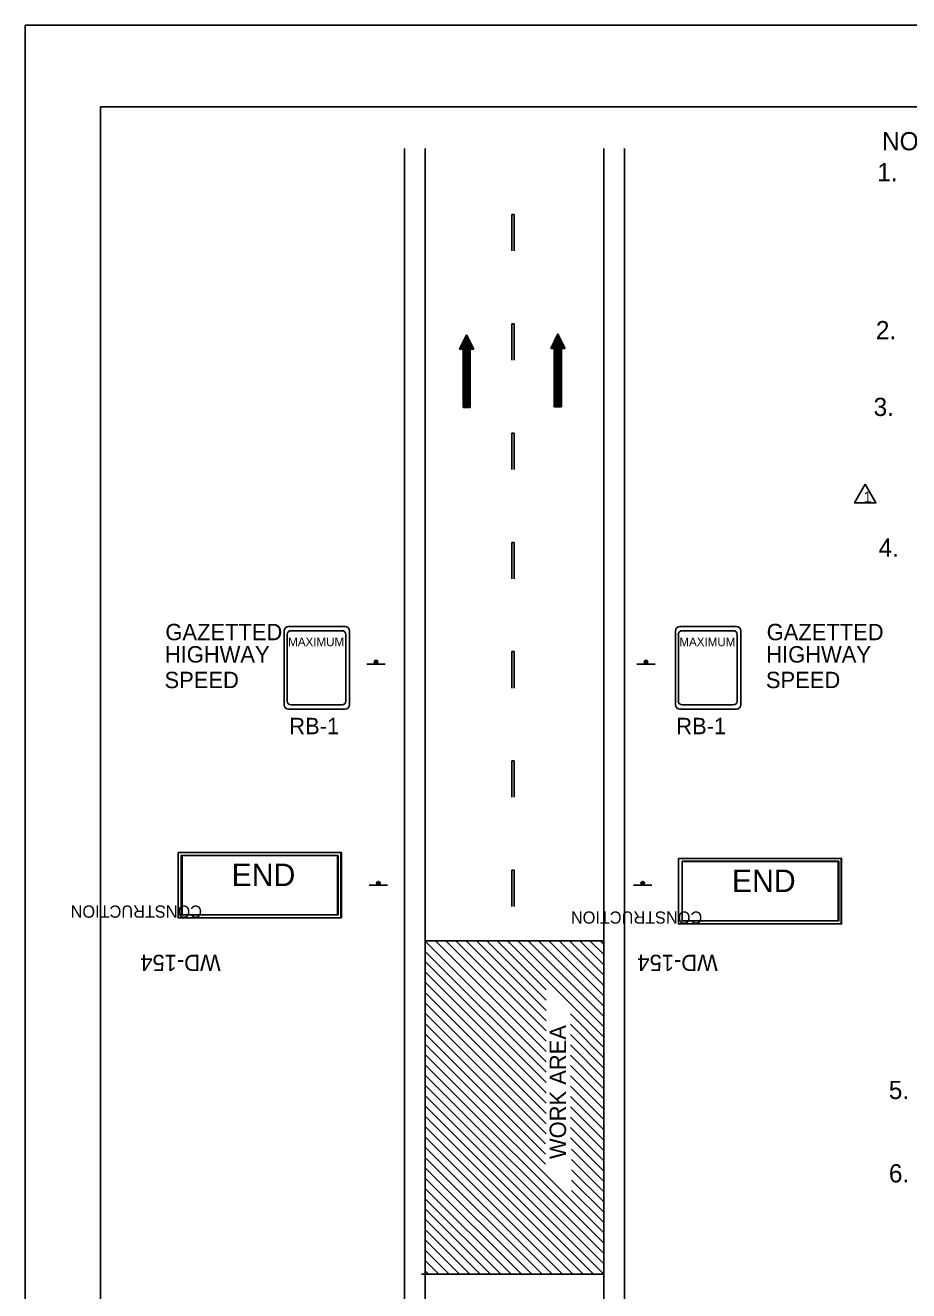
# Model space of a CAD drawing. Extents: x 1381 to 1597, y 125 to 404.
# Drawn here: x 1381.2 to 1498.5, y 235.9 to 403.9 of the extents above; entities that cross this region are included whole.
import ezdxf

# ---------------------------------------------------------------- set-up
doc = ezdxf.new("R2010")
doc.units = 0
for name, color, linetype in [('Level 1', 7, 'Continuous'), ('Level 10', 7, 'Continuous'), ('Level 2', 7, 'Continuous'), ('Level 44', 7, 'Continuous'), ('Level 60', 7, 'Continuous')]:
    doc.layers.add(name, color=color, linetype=linetype)

msp = doc.modelspace()

# ---------------------------------------------------------------- linework, layer by layer
at = {"layer": 'Level 1'}
msp.add_lwpolyline([(1492.72, 342.98), (1491.3, 340.5), (1494.14, 340.5)], close=True, dxfattribs=at)
at = {"layer": 'Level 10'}
for p, q in [((1431.55, 387.59), (1431.55, 334.55)), ((1434.3, 141.65), (1434.3, 387.59)), ((1458.01, 141.65), (1458.01, 387.59)), ((1460.73, 387.59), (1460.73, 387.59)), ((1460.73, 387.59), (1460.73, 141.65)), ((1439.79, 362.84), (1438.82, 360.91)), ((1439.06, 361.39), (1439.06, 360.91)), ((1439.18, 361.63), (1439.18, 360.91)), ((1439.31, 361.87), (1439.31, 353.16)), ((1439.43, 362.12), (1439.43, 353.16)), ((1439.55, 362.36), (1439.55, 353.16)), ((1439.67, 362.6), (1439.67, 353.16)), ((1439.79, 362.84), (1439.79, 353.16)), ((1439.79, 362.84), (1440.76, 360.91)), ((1439.91, 362.6), (1439.91, 353.16)), ((1440.03, 362.36), (1440.03, 353.16)), ((1440.15, 362.12), (1440.15, 353.16)), ((1440.27, 361.87), (1440.27, 353.16)), ((1440.39, 361.63), (1440.39, 360.91)), ((1440.52, 361.39), (1440.52, 360.91)), ((1451.92, 362.94), (1450.95, 361)), ((1451.19, 361.49), (1451.19, 361)), ((1451.31, 361.73), (1451.31, 361)), ((1451.43, 361.97), (1451.43, 353.26)), ((1451.56, 362.22), (1451.56, 353.26)), ((1451.68, 362.46), (1451.68, 353.26)), ((1451.8, 362.7), (1451.8, 353.26)), ((1451.92, 362.94), (1451.92, 353.26)), ((1451.92, 362.94), (1452.89, 361)), ((1452.04, 362.7), (1452.04, 353.26)), ((1452.16, 362.46), (1452.16, 353.26)), ((1452.28, 362.22), (1452.28, 353.26)), ((1452.4, 361.97), (1452.4, 353.26)), ((1452.52, 361.73), (1452.52, 361)), ((1452.64, 361.49), (1452.64, 361)), ((1438.82, 360.91), (1439.31, 360.91)), ((1438.94, 361.15), (1438.94, 360.91)), ((1439.31, 360.91), (1439.31, 353.16)), ((1440.27, 360.91), (1440.27, 353.16)), ((1440.27, 360.91), (1440.76, 360.91)), ((1440.64, 361.15), (1440.64, 360.91)), ((1450.95, 361), (1451.43, 361)), ((1451.07, 361.25), (1451.07, 361)), ((1451.43, 361), (1451.43, 353.26)), ((1452.4, 361), (1452.4, 353.26)), ((1452.4, 361), (1452.89, 361)), ((1452.77, 361.25), (1452.77, 361)), ((1439.31, 353.16), (1440.27, 353.16)), ((1451.43, 353.26), (1452.4, 353.26)), ((1431.55, 141.65), (1431.55, 334.55)), ((1458.01, 282.34), (1434.3, 282.34)), ((1450.35, 266.26), (1434.3, 282.31)), ((1450.35, 264.89), (1434.3, 280.94)), ((1450.35, 267.63), (1435.64, 282.34)), ((1450.35, 269), (1437.01, 282.34)), ((1450.35, 270.37), (1438.37, 282.34)), ((1450.35, 271.73), (1439.74, 282.34)), ((1450.35, 273.1), (1441.11, 282.34)), ((1450.35, 274.47), (1442.48, 282.34)), ((1450.35, 275.84), (1443.85, 282.34)), ((1458.01, 269.55), (1445.22, 282.34)), ((1458.01, 270.92), (1446.59, 282.34)), ((1458.01, 272.28), (1447.95, 282.34)), ((1458.01, 273.66), (1449.32, 282.34)), ((1458.01, 275.02), (1450.69, 282.34)), ((1458.01, 276.39), (1452.06, 282.34)), ((1458.01, 277.76), (1453.43, 282.34)), ((1458.01, 279.13), (1454.8, 282.34)), ((1458.01, 280.5), (1456.16, 282.34)), ((1458.01, 281.87), (1457.53, 282.34)), ((1450.35, 263.52), (1434.3, 279.57)), ((1450.35, 262.16), (1434.3, 278.2)), ((1450.35, 260.79), (1434.3, 276.83)), ((1450.35, 259.42), (1434.3, 275.47)), ((1450.35, 258.05), (1434.3, 274.1)), ((1450.35, 256.68), (1434.3, 272.73)), ((1458.01, 268.18), (1453.57, 272.62)), ((1450.26, 255.39), (1434.3, 271.36)), ((1458.01, 266.81), (1453.57, 271.25)), ((1450.26, 254.02), (1434.3, 269.99)), ((1458.01, 265.44), (1453.57, 269.88)), ((1450.26, 252.66), (1434.3, 268.62)), ((1458.01, 243.54), (1434.3, 267.25)), ((1458.01, 264.07), (1453.57, 268.51)), ((1458.01, 242.18), (1434.3, 265.88)), ((1458.01, 262.7), (1453.57, 267.14)), ((1458.01, 261.34), (1453.57, 265.77)), ((1458.01, 240.81), (1434.3, 264.51)), ((1458.01, 259.97), (1453.57, 264.4)), ((1458.01, 239.44), (1434.3, 263.15)), ((1458.01, 258.6), (1453.57, 263.04)), ((1458.01, 238.07), (1434.3, 261.78)), ((1458.01, 257.23), (1453.57, 261.67)), ((1458.01, 261.34), (1458, 261.34)), ((1456.64, 238.07), (1434.3, 260.41)), ((1455.27, 238.07), (1434.3, 259.04)), ((1458.01, 255.86), (1453.57, 260.3)), ((1458.01, 254.49), (1453.57, 258.93)), ((1453.9, 238.07), (1434.3, 257.67)), ((1458.01, 253.12), (1453.57, 257.56)), ((1452.53, 238.07), (1434.3, 256.31)), ((1458.01, 251.75), (1453.57, 256.19)), ((1451.16, 238.07), (1434.3, 254.94)), ((1458.01, 250.39), (1453.72, 254.67)), ((1449.8, 238.07), (1434.3, 253.57)), ((1448.43, 238.07), (1434.3, 252.2)), ((1458.01, 249.02), (1453.72, 253.3)), ((1447.06, 238.07), (1434.3, 250.83)), ((1458.01, 247.65), (1453.72, 251.93)), ((1458.01, 246.28), (1453.72, 250.56)), ((1445.69, 238.07), (1434.3, 249.46)), ((1458.01, 244.91), (1453.72, 249.19)), ((1444.32, 238.07), (1434.3, 248.09)), ((1442.95, 238.07), (1434.3, 246.72)), ((1441.58, 238.07), (1434.3, 245.36)), ((1440.21, 238.07), (1434.3, 243.99)), ((1438.85, 238.07), (1434.3, 242.62)), ((1437.48, 238.07), (1434.3, 241.25)), ((1436.11, 238.07), (1434.3, 239.88)), ((1458.01, 238.07), (1433.81, 238.07)), ((1434.74, 238.07), (1434.3, 238.51)), ((1458.01, 238.07), (1445.91, 238.07))]:
    msp.add_line(p, q, dxfattribs=at)
at = {"layer": 'Level 2'}
for p, q in [((1445.8, 378.81), (1445.8, 373.97)), ((1446.09, 378.81), (1445.8, 378.81)), ((1446.09, 373.97), (1446.09, 378.81)), ((1445.8, 364.29), (1445.8, 359.45)), ((1446.09, 364.29), (1445.8, 364.29)), ((1446.09, 359.45), (1446.09, 364.29)), ((1445.8, 349.78), (1445.8, 344.94)), ((1446.09, 349.78), (1445.8, 349.78)), ((1446.09, 344.94), (1446.09, 349.78)), ((1445.8, 335.26), (1445.8, 330.43)), ((1446.09, 335.26), (1445.8, 335.26)), ((1446.09, 330.43), (1446.09, 335.26)), ((1445.8, 320.75), (1445.8, 315.91)), ((1446.09, 320.75), (1445.8, 320.75)), ((1446.09, 315.91), (1446.09, 320.75)), ((1445.8, 306.24), (1445.8, 301.4)), ((1446.09, 306.24), (1445.8, 306.24)), ((1446.09, 301.4), (1446.09, 306.24)), ((1445.8, 291.72), (1445.8, 286.88)), ((1446.09, 291.72), (1445.8, 291.72)), ((1446.09, 286.88), (1446.09, 291.72))]:
    msp.add_line(p, q, dxfattribs=at)
for points in [[(1423.15, 285.38), (1401.49, 285.38), (1401.49, 294.08), (1423.15, 294.08)], [(1401.49, 294.06), (1423.08, 294.06), (1423.08, 285.38), (1401.49, 285.38)], [(1422.63, 285.77), (1401.86, 285.77), (1401.86, 293.68), (1422.63, 293.68)], [(1402, 293.67), (1422.71, 293.67), (1422.71, 285.78), (1402, 285.78)], [(1467.92, 293.29), (1489.58, 293.29), (1489.58, 284.59), (1467.92, 284.59)], [(1467.92, 293.27), (1489.52, 293.27), (1489.52, 284.59), (1467.92, 284.59)], [(1468.43, 292.9), (1489.21, 292.9), (1489.21, 284.99), (1468.43, 284.99)], [(1468.43, 292.88), (1489.14, 292.88), (1489.14, 284.99), (1468.43, 284.99)]]:
    msp.add_lwpolyline(points, close=True, dxfattribs=at)
at = {"layer": 'Level 44'}
for p, q in [((1415.56, 313.69), (1415.56, 323.49)), ((1415.94, 314.19), (1415.94, 323.01)), ((1416.14, 324.07), (1423.65, 324.07)), ((1416.47, 323.53), (1423.23, 323.53)), ((1423.76, 323.01), (1423.76, 314.19)), ((1424.24, 323.49), (1424.24, 313.69)), ((1467.51, 313.69), (1467.51, 323.49)), ((1467.9, 314.19), (1467.9, 323.01)), ((1468.09, 324.07), (1475.61, 324.07)), ((1468.42, 323.53), (1475.19, 323.53)), ((1475.71, 323.01), (1475.71, 314.19)), ((1476.19, 323.49), (1476.19, 313.69)), ((1426.55, 319.09), (1428.97, 319.09)), ((1462.39, 319.09), (1464.81, 319.09)), ((1415.56, 313.69), (1415.56, 313.69)), ((1415.94, 314.19), (1415.94, 314.19)), ((1423.65, 313.11), (1416.14, 313.11)), ((1416.27, 313.36), (1416.27, 313.36)), ((1423.23, 313.67), (1416.47, 313.67)), ((1467.51, 313.69), (1467.51, 313.69)), ((1467.9, 314.19), (1467.9, 314.19)), ((1475.61, 313.11), (1468.09, 313.11)), ((1468.23, 313.36), (1468.23, 313.36)), ((1475.19, 313.67), (1468.42, 313.67)), ((1426.85, 289.71), (1429.27, 289.71)), ((1461.96, 289.71), (1464.38, 289.71))]:
    msp.add_line(p, q, dxfattribs=at)
for centre, radius in [((1427.76, 319.36), 0.242), ((1427.76, 319.36), 0.121), ((1463.61, 319.36), 0.242), ((1463.61, 319.36), 0.121), ((1428.07, 289.98), 0.242), ((1428.07, 289.98), 0.121), ((1463.18, 289.98), 0.242), ((1463.18, 289.98), 0.121)]:
    msp.add_circle(centre, radius, dxfattribs=at)
for centre, radius, start, end in [((1416.14, 323.49), 0.58, 90, 180), ((1416.47, 323.01), 0.522, 90, 180), ((1423.23, 323.01), 0.522, 360, 90), ((1423.66, 323.49), 0.58, 360, 90), ((1468.09, 323.49), 0.58, 90, 180), ((1468.42, 323.01), 0.522, 90, 180), ((1475.19, 323.01), 0.522, 360, 90), ((1475.61, 323.49), 0.58, 360, 90), ((1416.14, 313.69), 0.58, 180, 270), ((1416.47, 314.19), 0.522, 180, 270), ((1423.23, 314.19), 0.522, 270, 360), ((1423.66, 313.69), 0.58, 270, 360), ((1468.09, 313.69), 0.58, 180, 270), ((1468.42, 314.19), 0.522, 180, 270), ((1475.19, 314.19), 0.522, 270, 360), ((1475.61, 313.69), 0.58, 270, 360)]:
    msp.add_arc(centre, radius, start, end, dxfattribs=at)
at = {"layer": 'Level 60'}
for points in [[(1597.18, 403.94), (1381.18, 403.94), (1381.18, 124.94), (1597.18, 124.94)], [(1578.06, 393.13), (1391.18, 393.13), (1391.18, 135.75), (1578.06, 135.75)]]:
    msp.add_lwpolyline(points, close=True, dxfattribs=at)

# ---------------------------------------------------------------- texts
at = {"layer": 'Level 1'}
msp.add_text('1', height=1.45, rotation=360, dxfattribs=at).set_placement((1492.49, 340.56))
at = {"layer": 'Level 10'}
for s, p in [('NOTES:', (1494.95, 387.34)), ('1.', (1494.32, 383.23)), ('2.', (1494.13, 362.24)), ('3.', (1493.83, 352.05)), ('4.', (1494.5, 333.36)), ('5.', (1495.85, 261.32)), ('6.', (1495.86, 250.25))]:
    msp.add_text(s, height=2.419, dxfattribs=at).set_placement(p)
for s, height, rotation, p in [('GAZETTED', 2.177, 360, (1399.78, 322.26)), ('GAZETTED', 2.177, 360, (1479.63, 322.26)), ('HIGHWAY', 2.178, 360, (1399.71, 319.3)), ('HIGHWAY', 2.178, 360, (1479.57, 319.3)), ('SPEED', 2.177, 360, (1399.67, 315.9)), ('SPEED', 2.177, 360, (1479.53, 315.9)), ('RB-1', 2.177, 360, (1416.23, 309.78)), ('RB-1', 2.177, 360, (1467.62, 309.78)), ('WD-154', 2.177, 180, (1407.13, 280.49)), ('WD-154', 2.177, 180, (1473.14, 280.49)), ('WORK AREA', 2.178, 90, (1452.99, 253.35))]:
    msp.add_text(s, height=height, rotation=rotation, dxfattribs=at).set_placement(p)
at = {"layer": 'Level 44'}
for s, height, rotation, p in [('MAXIMUM', 1.15, 360, (1416.09, 321.47)), ('MAXIMUM', 1.15, 360, (1468.04, 321.47)), ('END', 3, 360, (1408.57, 289.6)), ('END', 3, 360, (1475.01, 288.81)), ('CONSTRUCTION', 1.62, 180, (1404.65, 287.03)), ('CONSTRUCTION', 1.62, 180, (1471.08, 286.24))]:
    msp.add_text(s, height=height, rotation=rotation, dxfattribs=at).set_placement(p)

doc.saveas('drawing.dxf')
